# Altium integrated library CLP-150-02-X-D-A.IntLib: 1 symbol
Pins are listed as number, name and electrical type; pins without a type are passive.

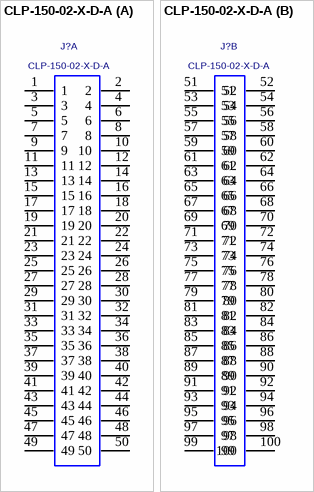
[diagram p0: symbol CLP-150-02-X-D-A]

## CLP-150-02-X-D-A
designator J?
LOW PROFILE SOCKET STRIP, .050"(1.27mm) PITCH, 100 PINS, VERTICAL; MANUFACTURER: SAMTEC; DESCRIPTION2: ALIGNMENT PINS
footprint CLP-150-02-X-D-A
part A pins: 1, 2, 3, 4, 5, 6, 7, 8, 9, 10, 11, 12, 13, 14, 15, 16, 17, 18, 19, 20, 21, 22, 23, 24, 25, 26, 27, 28, 29, 30, 31, 32, 33, 34, 35, 36, 37, 38, 39, 40, 41, 42, 43, 44, 45, 46, 47, 48, 49, 50
part B pins: 51, 52, 53, 54, 55, 56, 57, 58, 59, 60, 61, 62, 63, 64, 65, 66, 67, 68, 69, 70, 71, 72, 73, 74, 75, 76, 77, 78, 79, 80, 81, 82, 83, 84, 85, 86, 87, 88, 89, 90, 91, 92, 93, 94, 95, 96, 97, 98, 99, 100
